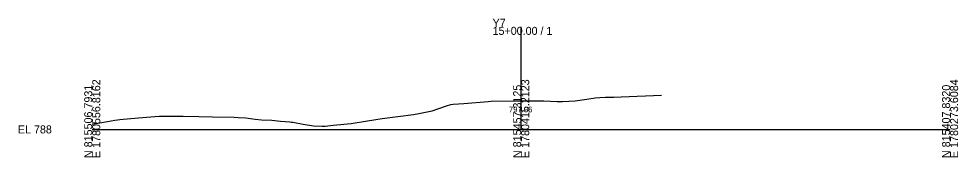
# Model space of a CAD drawing. Extents: x -26 to 2903, y -10 to 5536.
# Drawn here: x -25.7 to 302.8, y 4990.3 to 5038.6 of the extents above; entities that cross this region are included whole.
import ezdxf

# ---------------------------------------------------------------- set-up
doc = ezdxf.new("R2010")
doc.units = 0
for name, color, linetype in [('Exist Cross Section Cell', 7, 'Continuous'), ('Exist XS Center Line Elevation Label', 7, 'Continuous'), ('Exist XS Ground Line', 7, 'Continuous')]:
    doc.layers.add(name, color=color, linetype=linetype)

msp = doc.modelspace()

# ---------------------------------------------------------------- linework, layer by layer
at = {"layer": 'Exist Cross Section Cell'}
for p, q in [((150, 5000), (150, 5035.8)), ((0, 5000), (150, 5000)), ((150, 5000), (300, 5000))]:
    msp.add_line(p, q, dxfattribs=at)
at = {"layer": 'Exist XS Ground Line'}
for p, q in [((168.93, 5009.97), (173.01, 5010.6)), ((173.01, 5010.6), (175.89, 5011.04)), ((175.89, 5011.04), (177.46, 5011.12)), ((177.46, 5011.12), (179.48, 5011.23)), ((179.48, 5011.23), (182.35, 5011.26)), ((182.35, 5011.26), (184.98, 5011.35)), ((184.98, 5011.35), (199.13, 5011.93)), ((118.93, 5006.47), (123.89, 5008.2)), ((123.89, 5008.2), (125.45, 5008.69)), ((125.45, 5008.69), (126.19, 5008.8)), ((126.19, 5008.8), (129.94, 5009.08)), ((129.94, 5009.08), (138.42, 5009.78)), ((138.42, 5009.78), (139.5, 5009.84)), ((139.5, 5009.84), (147.31, 5009.94)), ((147.31, 5009.94), (149.78, 5009.96)), ((149.78, 5009.96), (152.81, 5009.97)), ((152.81, 5009.97), (157.97, 5009.98)), ((157.97, 5009.98), (162.56, 5009.79)), ((162.56, 5009.79), (164.41, 5009.79)), ((164.41, 5009.79), (168.93, 5009.97)), ((9.62, 5003.47), (10.84, 5003.57)), ((10.84, 5003.57), (17.52, 5004.19)), ((17.52, 5004.19), (21.89, 5004.51)), ((21.89, 5004.51), (23.44, 5004.57)), ((23.44, 5004.57), (25.7, 5004.66)), ((25.7, 5004.66), (31.77, 5004.61)), ((31.77, 5004.61), (37.22, 5004.56)), ((37.22, 5004.56), (42, 5004.44)), ((42, 5004.44), (49.58, 5004.25)), ((49.58, 5004.25), (51.05, 5004.17)), ((51.05, 5004.17), (53.74, 5004.02)), ((53.74, 5004.02), (57.02, 5003.54)), ((96.25, 5002.96), (101.39, 5003.77)), ((101.39, 5003.77), (112.35, 5005.25)), ((112.35, 5005.25), (112.98, 5005.34)), ((112.98, 5005.34), (113.62, 5005.43)), ((113.62, 5005.43), (118.93, 5006.47)), ((0, 5001.88), (5.36, 5002.8)), ((5.36, 5002.8), (7.9, 5003.17)), ((7.9, 5003.17), (8.82, 5003.4)), ((8.82, 5003.4), (9.62, 5003.47)), ((57.02, 5003.54), (59.15, 5003.38)), ((59.15, 5003.38), (62.82, 5003.2)), ((62.82, 5003.2), (65.79, 5002.91)), ((65.79, 5002.91), (69.07, 5002.62)), ((69.07, 5002.62), (69.69, 5002.57)), ((69.69, 5002.57), (70.16, 5002.47)), ((70.16, 5002.47), (73.75, 5001.83)), ((73.75, 5001.83), (77.43, 5001.19)), ((77.43, 5001.19), (80.46, 5001.16)), ((80.46, 5001.16), (81.4, 5001.08)), ((81.4, 5001.08), (84.27, 5001.47)), ((84.27, 5001.47), (90.6, 5002.11)), ((90.6, 5002.11), (96.25, 5002.96))]:
    msp.add_line(p, q, dxfattribs=at)

# ---------------------------------------------------------------- texts
at = {"layer": 'Exist Cross Section Cell'}
for s, p in [('Y7', (140, 5035.8)), ('15+00.00 / 1', (140, 5033)), ('EL 788', (-26, 4998.6))]:
    msp.add_text(s, height=2.8, dxfattribs=at).set_placement(p)
for s, p in [('E 1780556.8162', (2.8, 4990)), ('E 1780415.2123', (152.8, 4990)), ('E 1780273.6084', (302.8, 4990)), ('N 815506.7931', (0, 4990)), ('N 815457.3125', (150, 4990)), ('N 815407.8320', (300, 4990))]:
    msp.add_text(s, height=2.8, rotation=90, dxfattribs=at).set_placement(p)
at = {"layer": 'Exist XS Center Line Elevation Label'}
msp.add_text('797.96', height=2, dxfattribs=at).set_placement((145.73, 5005.96))

doc.saveas('drawing.dxf')
